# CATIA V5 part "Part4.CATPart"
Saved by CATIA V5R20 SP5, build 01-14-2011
Part number: Part4
Bounding box of the stored display mesh (mm): x -27.797 to -6.726, y -3.361 to 3.361, z 93.957 to 100.74
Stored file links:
  C:\Documents and Settings\Student\桌面\考试\Part4.CATPart
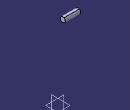
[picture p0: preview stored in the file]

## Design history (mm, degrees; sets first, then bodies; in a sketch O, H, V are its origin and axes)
Body1 (main body)
  Sketch1 on zx-plane, origin (0, 0, 0), H (-1, 0, 0), V (0, 0, 1)
    line L1 (6.7256, 100.7684) -> (27.7972, 100.7684)
    line L2 (27.7972, 100.7684) -> (27.7972, 97.3487)
    line L3 (27.7972, 97.3487) -> (6.7256, 97.3487)
    line L4 (6.7256, 97.3487) -> (6.7256, 100.7684)
    horizontal: L1 H, L3 H
    vertical: L2 V, L4 V
  Shaft1: profile Sketch1, axis Sketch1.L3, angle 360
